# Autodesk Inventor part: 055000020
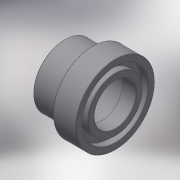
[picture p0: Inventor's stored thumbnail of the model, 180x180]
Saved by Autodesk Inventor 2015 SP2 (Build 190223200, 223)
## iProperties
Created: 2017-10
Part Number: 055000020
Material: Generic
Description: PLASSON FLANGE AD.+O-RING-CE 20
Document SubType Name: Modeling
Designer: KIM
Density: 1 g/cm^3
Appearance: Default
Author: KIM
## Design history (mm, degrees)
derived "055000.ipt"
feature "Solid1::055000.ipt"
tag "TaggingFeature1"
body "Solid1"
other parameters: "d0" = 22, "d1" = 27, "d3" = 18, "d5" = 16, "d6" = 34, "d8" = 3, "d11" = 0.2, "d12" = 3, "d15" = 2.4, "E_" = 27, "E_1" = 34, "l_" = 16, "H_" = 22, "d14" = 8
